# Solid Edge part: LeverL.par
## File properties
Author: Wojciech Szerszeń
Template: ISO Metric Part.par
Last saved by: wojci
Revision: 7
Application: Solid Edge
Username: Wojciech Szerszeń
Accuracy: 0.990
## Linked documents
Lever.par
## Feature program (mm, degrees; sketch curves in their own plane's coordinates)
part copy "CopiedPart_1"
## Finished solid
Body 1: solid body, 52 faces, 142 edges, 88 vertices.
  Faces by surface: plane 25, cylinder 20, cone 5, torus 2
  Edges by curve: line 72, circle 52, intersection 17, ellipse 1
Bounding box of the edges (mm; curved faces can reach further): 82.182 x 52.500 x 33.164, from (-43.2989, -52.5, -13.028) to (38.8829, 0, 20.1362).
Cylindrical faces by radius (mm): R1 x3, R1.2295 x3, R1.5 x3, R1.7 x1, R3 x1, R3.5 x2, R5 x2, R6.5002 x2, R9 x1, R10 x1, R12 x1
Conical faces (half-angle, radius in mm at the cone's reference point): 45 deg R10 x1, 45 deg R10.5 x1, 45 deg R12 x2, 45 deg R15 x1
Toroidal faces (ring radius, tube radius in mm): R2.7 r1 x2
Planar faces by outward normal: +y 5, -y 5, oblique 15
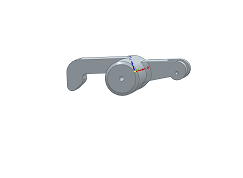
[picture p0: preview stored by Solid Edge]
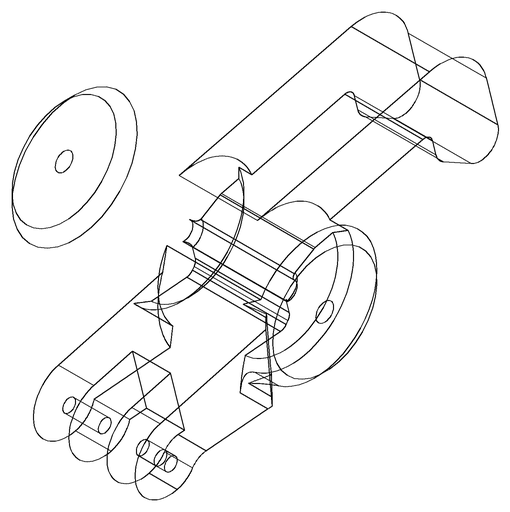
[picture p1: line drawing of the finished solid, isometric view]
